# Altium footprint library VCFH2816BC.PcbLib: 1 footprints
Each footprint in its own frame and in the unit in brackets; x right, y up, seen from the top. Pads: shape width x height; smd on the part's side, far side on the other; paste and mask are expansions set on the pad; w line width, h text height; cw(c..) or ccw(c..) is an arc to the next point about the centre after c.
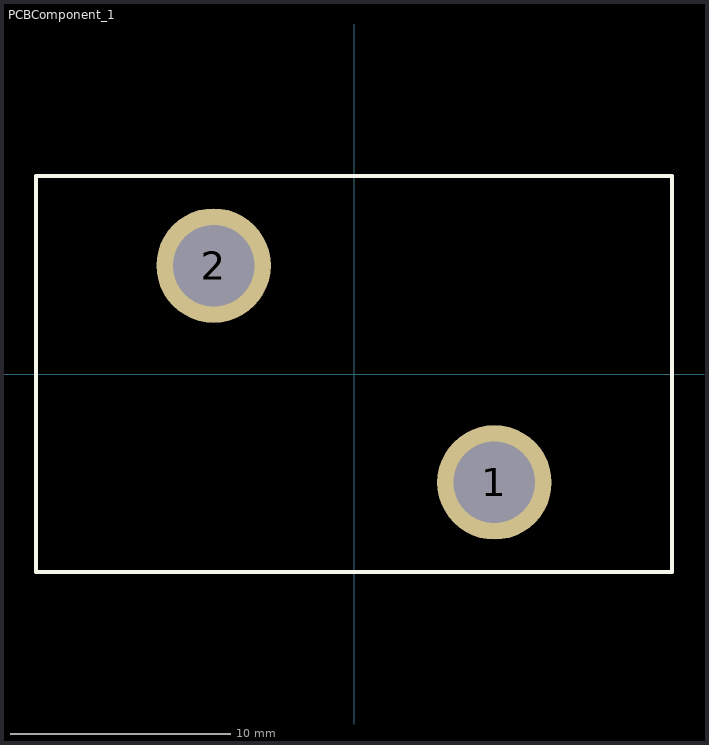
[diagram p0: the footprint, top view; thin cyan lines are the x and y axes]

## PCBComponent_1 [mm]
pads (2):
  round 5.2 hole 3.7: 1(6.375,-4.925) 2(-6.375,4.925)
Top Overlay:
  lines w0.178: -14.45,-9 14.45,-9 14.45,9 -14.45,9 -14.45,-9
M5 Assembly Top:
  text ".Designator" at -5.231,-0.83 h1.02
3D body: height 23.6, standoff 0, extent -14.2,-8.9 14.2,8.8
